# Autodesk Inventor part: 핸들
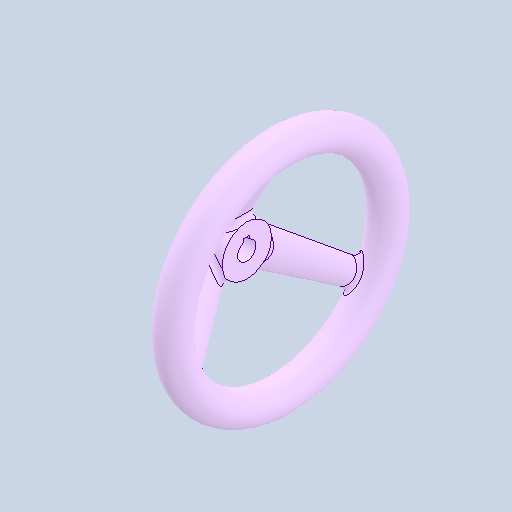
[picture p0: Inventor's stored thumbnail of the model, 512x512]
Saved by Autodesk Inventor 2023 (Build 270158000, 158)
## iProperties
Created: 2024-07
Part Number: 핸들
Material: 강철, 연강
Document SubType Name: Modeling
Designer: home
Density: 7.85 g/cm^3
Appearance: 기본값
Author: jhkim
Sending System: Autodesk Inventor 2025
Preprocessor: ST-DEVELOPER v20
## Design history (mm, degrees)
feature "솔리드1"
node "솔리드2"
